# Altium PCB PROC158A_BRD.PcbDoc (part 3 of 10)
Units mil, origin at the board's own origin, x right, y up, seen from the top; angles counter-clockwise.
Board outline 3346.45 x 4921.26 mil, 8 copper layers (Top Layer, GND1, SIG1, PWR1, PWR2, SIG2, GND2, Bottom Layer), stack 54.534 mil thick; 718 components, 459 nets, 2307 pads, 1179 vias.
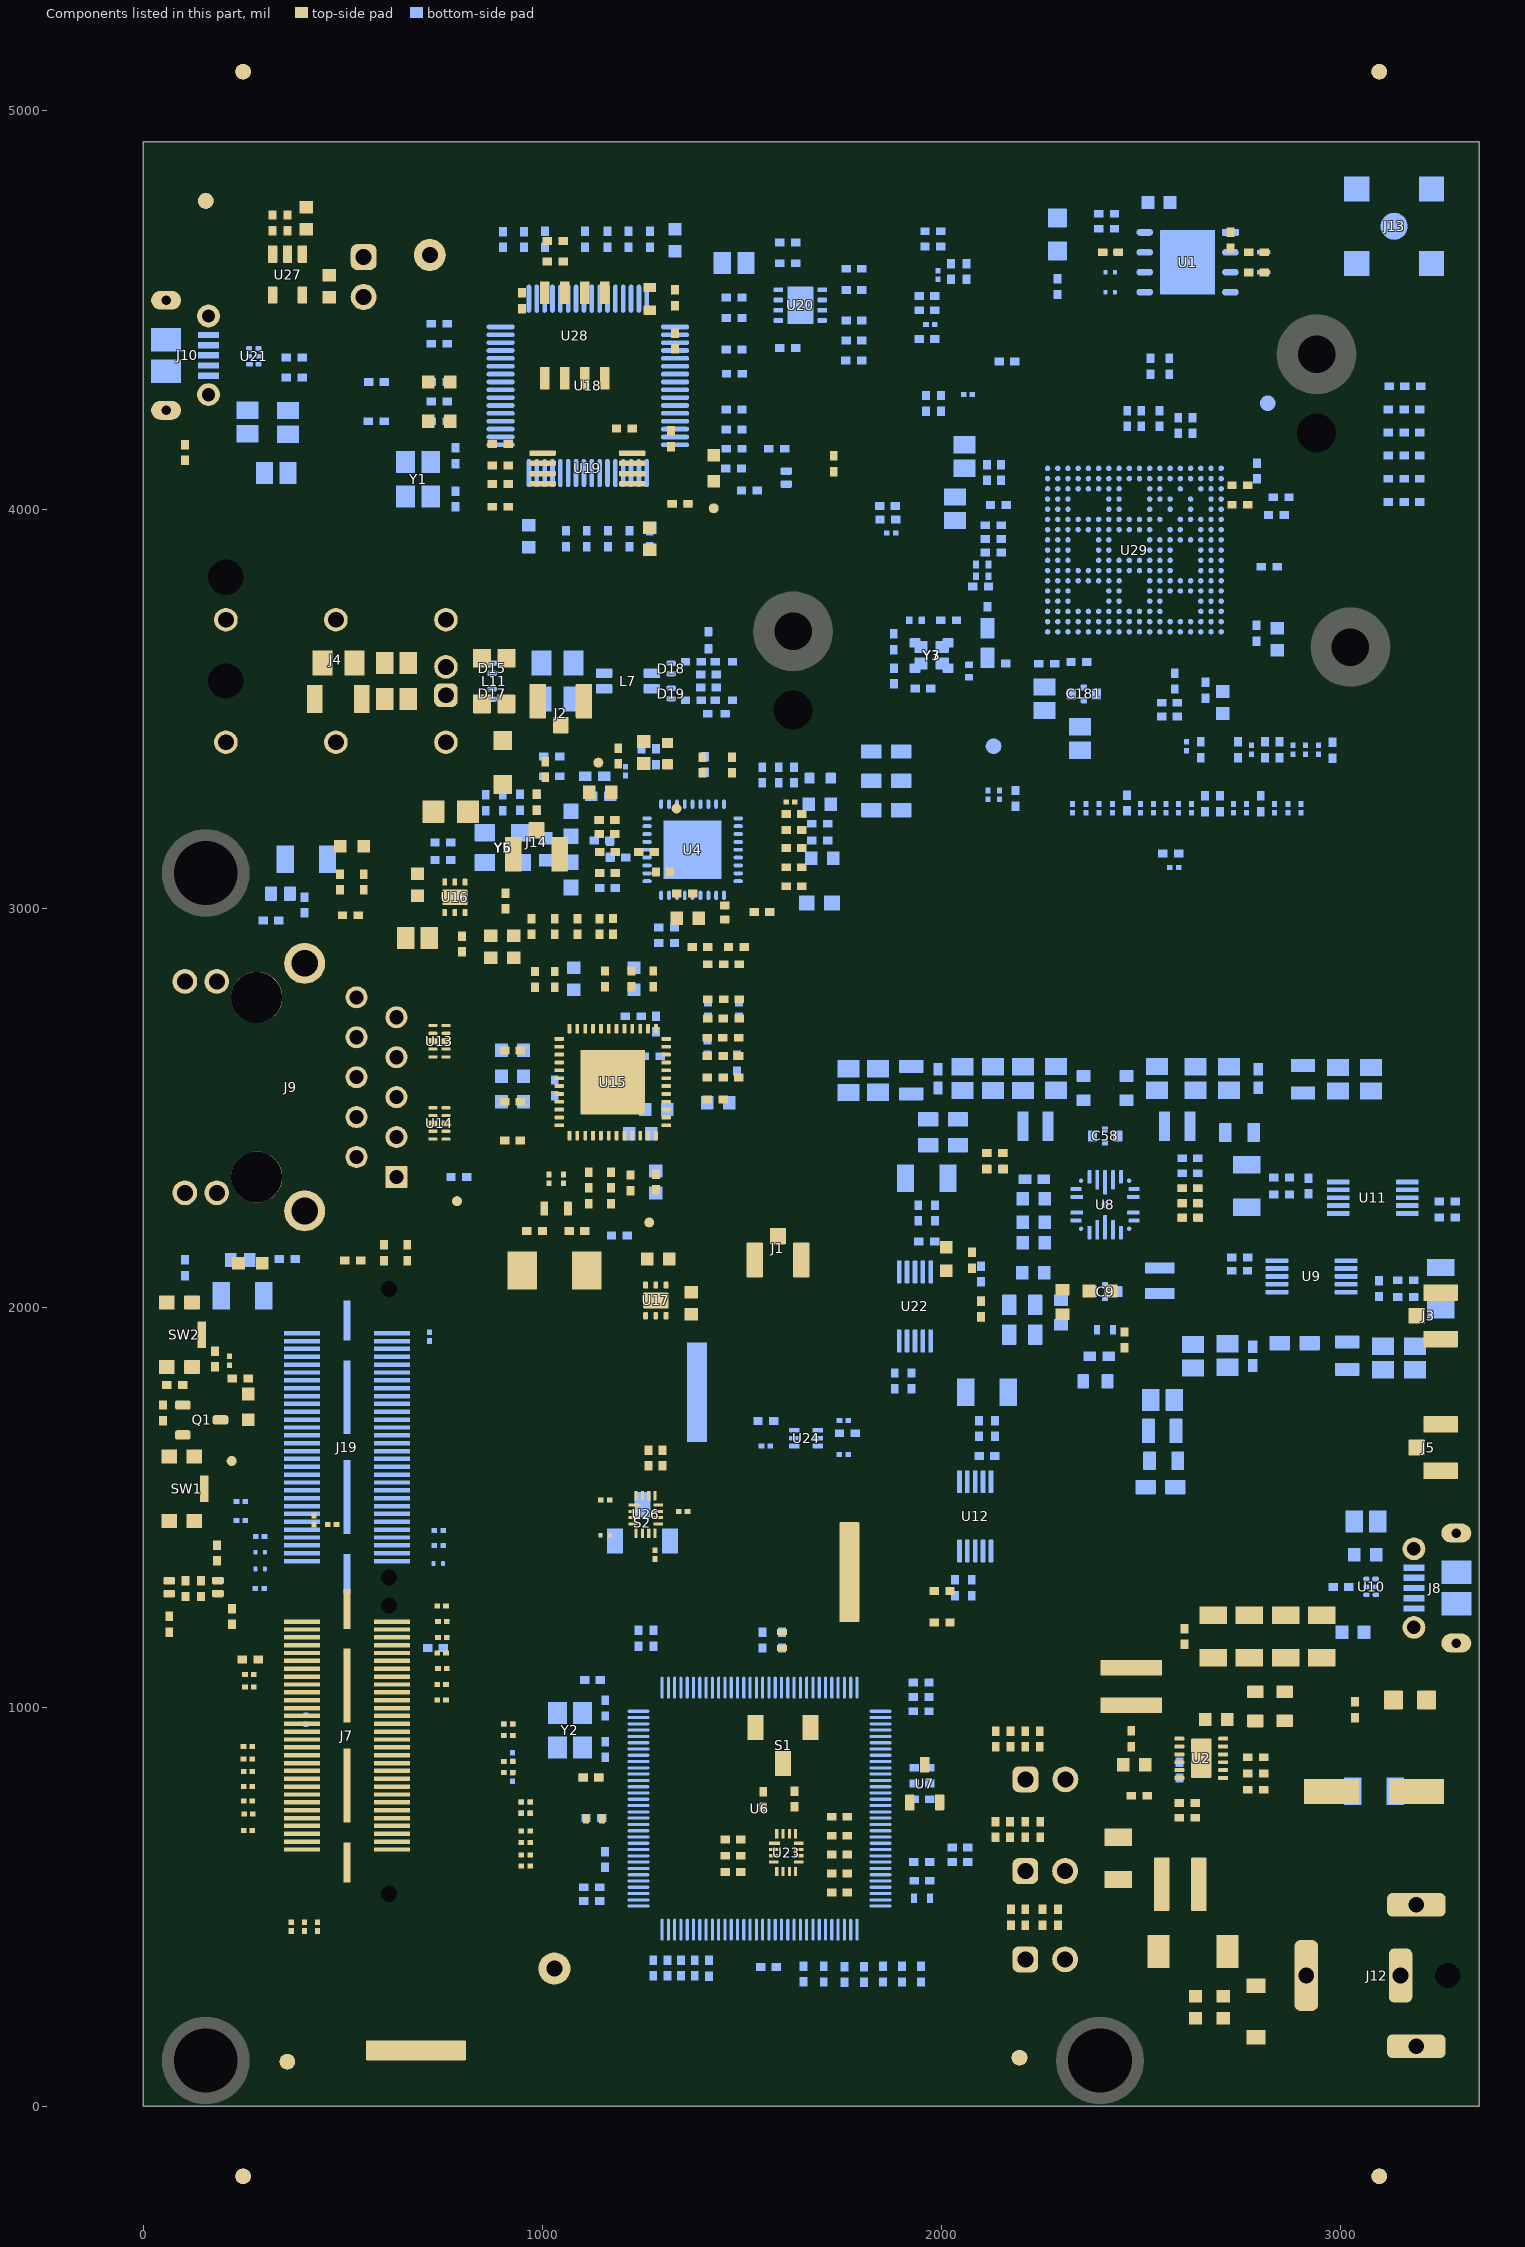
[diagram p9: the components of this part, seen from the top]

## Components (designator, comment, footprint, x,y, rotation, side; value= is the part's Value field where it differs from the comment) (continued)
R508 "CRCW02014K70FKED" 0201_033L 244.45,1467.61 r0 bottom value=4.70k
R512 "CRCW02014K70FKED" 0201_033L 740.29,1441.93 r0 bottom value=4.70k
S1 "CJS-1201TA" SW_CJS_1201A 1602.81,903.98 r180 top
S2 "CJS-1201TA" SW_CJS_1201A 1250.43,1461.4 r180 bottom
SW1 "KMR243GLFG" SW_KMR243GLFG 96.47,1547 r270 top
SW2 "KMR243GLFG" SW_KMR243GLFG 90.65,1932.78 r270 top
TP1 "TESTPOINT" TP_25MIL-SMT 1429,4003 r0 top
TP2 "TESTPOINT" TP_25MIL-SMT 1336,3251 r0 top
TP3 "TESTPOINT" TP_25MIL-SMT 1140,3365.81 r90 top
TP4 "TESTPOINT" TP_25MIL-SMT 221.49,1616.57 r180 top
TP5 "TESTPOINT" TP_25MIL-SMT 1267.43,2214.09 r90 top
TP6 "TESTPOINT" TP_25MIL-SMT 786.03,2267.32 r90 top
TP7 "5001" Keystone5001 717.82,4637.51 r90 bottom
TP9 "5001" Keystone5001 1030,345 r90 top
U1 "GD25B64CWAG" FP-GD25B64CWAG_WSON8-IPC_C 2616.14,4619.33 r180 bottom locked
U2 "LM63635DQDRRRQ1" DRR0012E-MFG 2650.36,871.52 r0 top
U4 "DP83TG720SWRNDRQ1" RND0036A 1376.2,3147.57 r0 bottom
U6 "TM4C1294NCPDTT3" PDT0128A 1543.78,745.39 r180 bottom
U7 "LM4040C25QDBZR" DBZ0003A_N 1957.44,808.38 r90 top
U8 "LP87725110RAGRQ1" RAG0024A-MFG 2409.48,2258.31 r180 bottom
U9 "INA228AIDGST" DGS0010A-MFG 2926.57,2078.86 r0 bottom
U10 "TPD4E004DRYR" DRY0006A 3075.82,1301 r180 bottom
U11 "INA228AIDGST" DGS0010A-MFG 3080,2275.91 r180 bottom
U12 "INA228AIDGST" DGS0010A-MFG 2084.09,1477.8 r90 bottom
U13 "TPD4E05U06DQAR" DQA0010A 742.07,2668.11 r0 top
U14 "TPD4E05U06DQAR" DQA0010A 742.07,2462.03 r0 top
U15 "DP83867ERGZR" RGZ0048B 1175.93,2565.54 r0 top
U16 "TPS73501DRVR" DRV0006A 780.58,3028.35 r90 top
U17 "TLV73310PQDRVRQ1" DRV0006A 1283.94,2018.66 r270 top
U18 "FT4232HL" LQFP64_N 1113.67,4309.69 r0 bottom
U19 "93LC46B-I/ST" TSSOP-8 1112.63,4102.86 r0 top
U20 "TPS79601DRBR" DRB0008B 1645.9,4511.81 r0 bottom
U21 "TPD4E004DRYR" DRY0006A 276.82,4383.75 r0 bottom
U22 "INA228AIDGST" DGS0010A-MFG 1933.06,2003.55 r90 bottom
U23 "TS3A5018RSVR" RSV0016A 1610.69,635.24 r0 top
U24 "TMP112AIDRLR" DRL0006A 1660.48,1673.65 r0 bottom
U26 "TS3A5018RSVR" RSV0016A 1258.31,1482.43 r0 top
U27 "TPS78417QDBVRQ1" DBV0005A-MFG 361.36,4588.41 r270 top
U28 "CAV24C02WE-GT3" SOIC-8 1080.83,4435.85 r90 top
U29 "xWR2544LOP" 0-IPC_C 2482.82,3898.25 r0 bottom locked
Y1 "NX3225SA-12.000M-STD-CRS-2" NDK_NX3225SA 688.79,4075.44 r0 bottom
Y2 "NX3225SA-16.000M-STD-CRS-2" NDK_NX3225SA 1068.77,941.56 r0 bottom
Y3 "NX2016SA-50M-STD-CZS-3" FP-NX2016SA-50M-STD-CZS-3_SMT4_2MM0_1MM6-MFG 1974.89,3634.94 r0 bottom
Y4 "ABM3-25.000MHZ-D2Y-T" XTAL_ABM3 1030.27,2093.9 r0 top
Y5 "ABM8AIG-25.000MHZ-12-2Z-T3" Abracon_ABM8AIG 901.05,3152.84 r270 bottom
Y6 "CDC6CE02500CDLE" DLE0004A-MFG 902,3152.81 r270 bottom
Y7 "CDC6CE05000CDLE" DLE0004A-MFG 1974.89,3634.2 r270 bottom
ZZ1 "This Assembly Note is for PCB labels only" AssemblyNoteLabel 187.12,5373.66 r0 top
ZZ2 "These assemblies are ESD sensitive, ESD precautions shall be observed." AssemblyNote 187.12,5264.77 r0 top
ZZ3 "These assemblies must be clean and free from flux and all contaminants. Use of no clean flux is not acceptable." AssemblyNote 187.12,5176.21 r0 top
ZZ4 "These assemblies must comply with workmanship standards IPC-A-610 Class 2, unless otherwise specified." AssemblyNote 187.12,5087.66 r0 top

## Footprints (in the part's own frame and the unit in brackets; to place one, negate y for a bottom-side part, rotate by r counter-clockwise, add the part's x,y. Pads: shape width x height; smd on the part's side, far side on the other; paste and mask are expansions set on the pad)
0-IPC_C [mm]
  round 0.349 smd paste+0 mask+0: A1(-5.525,5.2) A2(-4.875,5.2) A3(-4.225,5.2) A4(-3.575,5.2) A5(-2.925,5.2) A6(-2.275,5.2) A7(-1.625,5.2) A8(-0.975,5.2) A9(-0.325,5.2) A10(0.325,5.2) A11(0.975,5.2) A12(1.625,5.2) A13(2.275,5.2) A14(2.925,5.2) A15(3.575,5.2) A16(4.225,5.2) A17(4.875,5.2) A18(5.525,5.2) B1(-5.525,4.55) B2(-4.875,4.55) B3(-4.225,4.55) B4(-3.575,4.55) B5(-2.925,4.55) B6(-2.275,4.55) B7(-1.625,4.55) B8(-0.975,4.55) B9(-0.325,4.55) B10(0.325,4.55) B11(0.975,4.55) B12(1.625,4.55) B13(2.275,4.55) B14(2.925,4.55) B15(3.575,4.55) B16(4.225,4.55) B17(4.875,4.55) B18(5.525,4.55) C1(-5.525,3.9) C2(-4.875,3.9) C3(-4.225,3.9) C4(-3.575,3.9) C5(-2.925,3.9) C6(-2.275,3.9) C7(-1.625,3.9) C8(-0.975,3.9) C9(-0.325,3.9) C10(0.325,3.9) C11(0.975,3.9) C12(1.625,3.9) C16(4.225,3.9) C17(4.875,3.9) C18(5.525,3.9) D1(-5.525,3.25) D2(-4.875,3.25) D3(-4.225,3.25) D7(-1.625,3.25) D8(-0.975,3.25) D11(0.975,3.25) D12(1.625,3.25) D16(4.225,3.25) D17(4.875,3.25) D18(5.525,3.25) E1(-5.525,2.6) E2(-4.875,2.6) E3(-4.225,2.6) E7(-1.625,2.6) E8(-0.975,2.6) E11(0.975,2.6) E12(1.625,2.6) E13(2.275,2.6) E14(2.925,2.6) E15(3.575,2.6) E16(4.225,2.6) E17(4.875,2.6) E18(5.525,2.6) F1(-5.525,1.95) F2(-4.875,1.95) F3(-4.225,1.95) F4(-3.575,1.95) F5(-2.925,1.95) F6(-2.275,1.95) F7(-1.625,1.95) F8(-0.975,1.95) F11(0.975,1.95) F12(1.625,1.95) F13(2.275,1.95) F14(2.925,1.95) F15(3.575,1.95) F16(4.225,1.95) F17(4.875,1.95) F18(5.525,1.95) G1(-5.525,1.3) G2(-4.875,1.3) G3(-4.225,1.3) G4(-3.575,1.3) G5(-2.925,1.3) G6(-2.275,1.3) G7(-1.625,1.3) G8(-0.975,1.3) G9(-0.325,1.3) G10(0.325,1.3) G11(0.975,1.3) G12(1.625,1.3) G13(2.275,1.3) G16(4.225,1.3) G17(4.875,1.3) G18(5.525,1.3) H1(-5.525,0.65) H2(-4.875,0.65) H3(-4.225,0.65) H6(-2.275,0.65) H7(-1.625,0.65) H8(-0.975,0.65) H9(-0.325,0.65) H10(0.325,0.65) H11(0.975,0.65) H12(1.625,0.65) H13(2.275,0.65) H16(4.225,0.65) H17(4.875,0.65) H18(5.525,0.65) J1(-5.525,0) J2(-4.875,0) J3(-4.225,0) J6(-2.275,0) J7(-1.625,0) J11(0.975,0) J12(1.625,0) J13(2.275,0) J16(4.225,0) J17(4.875,0) J18(5.525,0) K2(-4.875,-0.65) K3(-4.225,-0.65) K6(-2.275,-0.65) K7(-1.625,-0.65) K11(0.975,-0.65) K12(1.625,-0.65) K13(2.275,-0.65) K14(2.925,-0.65) K15(3.575,-0.65) K16(4.225,-0.65) K17(4.875,-0.65) K18(5.525,-0.65) L1(-5.525,-1.3) L2(-4.875,-1.3) L3(-4.225,-1.3) L4(-3.575,-1.3) L5(-2.925,-1.3) L6(-2.275,-1.3) L7(-1.625,-1.3) L8(-0.975,-1.3) L9(-0.325,-1.3) L10(0.325,-1.3) L11(0.975,-1.3) L13(2.275,-1.3) L14(2.925,-1.3) L16(4.225,-1.3) L17(4.875,-1.3) L18(5.525,-1.3) M1(-5.525,-1.95) M2(-4.875,-1.95) M3(-4.225,-1.95) M4(-3.575,-1.95) M5(-2.925,-1.95) M6(-2.275,-1.95) M7(-1.625,-1.95) M8(-0.975,-1.95) M9(-0.325,-1.95) M10(0.325,-1.95) M11(0.975,-1.95) M12(1.625,-1.95) M14(2.925,-1.95) M15(3.575,-1.95) M16(4.225,-1.95) M17(4.875,-1.95) M18(5.525,-1.95) N1(-5.525,-2.6) N2(-4.875,-2.6) N3(-4.225,-2.6) N7(-1.625,-2.6) N8(-0.975,-2.6) N11(0.975,-2.6) N13(2.275,-2.6) N15(3.575,-2.6) N17(4.875,-2.6) N18(5.525,-2.6) P1(-5.525,-3.25) P2(-4.875,-3.25) P3(-4.225,-3.25) P7(-1.625,-3.25) P8(-0.975,-3.25) P11(0.975,-3.25) P12(1.625,-3.25) P13(2.275,-3.25) P15(3.575,-3.25) P17(4.875,-3.25) P18(5.525,-3.25) R1(-5.525,-3.9) R2(-4.875,-3.9) R3(-4.225,-3.9) R4(-3.575,-3.9) R5(-2.925,-3.9) R6(-2.275,-3.9) R7(-1.625,-3.9) R8(-0.975,-3.9) R11(0.975,-3.9) R12(1.625,-3.9) R14(2.925,-3.9) R16(4.225,-3.9) R17(4.875,-3.9) R18(5.525,-3.9) T1(-5.525,-4.55) T2(-4.875,-4.55) T3(-4.225,-4.55) T4(-3.575,-4.55) T5(-2.925,-4.55) T6(-2.275,-4.55) T7(-1.625,-4.55) T8(-0.975,-4.55) T9(-0.325,-4.55) T10(0.325,-4.55) T11(0.975,-4.55) T12(1.625,-4.55) T13(2.275,-4.55) T14(2.925,-4.55) T15(3.575,-4.55) T16(4.225,-4.55) T17(4.875,-4.55) T18(5.525,-4.55) U1(-5.525,-5.2) U2(-4.875,-5.2) U3(-4.225,-5.2) U4(-3.575,-5.2) U5(-2.925,-5.2) U6(-2.275,-5.2) U7(-1.625,-5.2) U8(-0.975,-5.2) U9(-0.325,-5.2) U10(0.325,-5.2) U11(0.975,-5.2) U12(1.625,-5.2) U13(2.275,-5.2) U14(2.925,-5.2) U15(3.575,-5.2) U16(4.225,-5.2) U17(4.875,-5.2) U18(5.525,-5.2)
  oval 0.349x0.349 smd paste+0 mask+0: K1(-5.525,-0.65)
  silkscreen extent -6.96,-6 6.2,6, body extent -6.2,-6 6.2,6, height 1.24
142-0711-201 [mil] "Emerson Connectivity recommended land pattern"
  round 68 smd: 1(0,0)
  rect 63x63 smd: 2(-93.5,-93.5) 2(-93.5,93.5) 2(93.5,-93.5) 2(93.5,93.5)
  Top Layer region: -47.5,64.83 -57.02,57.02 -67.05,44.8 -74.5,30.86 -79.09,15.73 -80.64,0 -79.09,-15.73 -74.5,-30.86 -67.05,-44.8 -57.02,-57.02 -47.5,-64.83 -47.5,-140 -140.5,-140 -140.5,140 -47.5,140
  Top Layer region: 140.5,-140 47.5,-140 47.5,-64.83 57.02,-57.02 67.05,-44.8 74.5,-30.86 79.09,-15.73 80.64,0 79.09,15.73 74.5,30.86 67.05,44.8 57.02,57.02 47.5,64.83 47.5,140 140.5,140
  body extent -125,-125 125,125, height 349
0201_033L [mm] "0201"
  rect 0.36x0.32 smd mask+0.048: 1(-0.28,0) 2(0.28,0)
  body extent -0.31,-0.16 0.31,0.16, height 0.33
0201L [mm] "Data from Kemet datasheet CC101_COM dated 7/28/11"
  rect 0.36x0.32 smd mask+0.048: 1(-0.28,0) 2(0.28,0)
  body extent -0.31,-0.16 0.31,0.16, height 0.26
0402 [mm] "0402 from SM-752 data"
  rect 0.8x0.6 smd: 1(-0.6,0) 2(0.6,0)
  silkscreen extent -1.22,-0.52 1.22,0.52, body extent -0.55,-0.3 0.55,0.3, height 0.6
0402_065L [mm] "0402"
  rect 0.6x0.5 smd: 1(-0.5,0) 2(0.5,0)
  body extent -0.55,-0.3 0.55,0.3, height 0.65
0402_070 [mil] "SMD, 2-Leads, Body 1.2x0.7mm, Height 0.7mm"
  rect 15x24 smd: 1(-20,0) 2(20,0)
  body extent -24,-14 24,14, height 28
0402L [mm] "0402 from SM-752 data"
  rect 0.6x0.5 smd: 1(-0.5,0) 2(0.5,0)
  body extent -0.55,-0.3 0.55,0.3, height 0.6
0402S [mil] "Based on C0402S footprint from PADS legacy"
  rect 15x24 smd: 1(-20,0) 2(20,0)
  body extent -22,-12 22,12, height 24
0603 [mm] "0603 from SM-752 data"
  rect 1x0.95 smd: 1(-0.8,0) 2(0.8,0)
  silkscreen extent -1.52,-0.69 1.52,0.69, body extent -0.87,-0.47 0.87,0.47, height 1
0603L [mm] "0603 from SM-752 data"
  rect 0.8x0.85 smd: 1(-0.7,0) 2(0.7,0)
  silkscreen extent -0.07,-0.33 0.07,0.33, body extent -0.87,-0.47 0.87,0.47, height 1
0805_155 [mm] "SMD, 2-Leads, Body 2x1.25mm"
  rrect12% 0.825x1.55 smd: 1(-0.875,0) 2(0.875,0)
  silkscreen extent -0.15,-0.77 0.15,0.77, body extent -1.15,-0.77 1.15,0.77, height 1.55
0805_HV [mil] "0805 with 30mil clearance between pads"
  rect 50x63 smd: 1(-40,0) 2(40,0)
  silkscreen extent -74,-40 74,40, body extent -43,-29 43,29, height 57
0805L [mm] "0805 from SM-752 data"
  rect 1.1x1.4 smd: 1(-0.75,0) 2(0.75,0)
  body extent -1.1,-0.72 1.1,0.72, height 1.45
1206_180L [mm] "1206_180"
  rect 1.1x1.75 smd: 1(-1.35,0) 2(1.35,0)
  silkscreen extent -0.4,-0.77 0.4,0.77, body extent -1.75,-0.95 1.75,0.95, height 1.8
1206L [mm] "1206 from SM-752 data"
  rect 1.1x1.75 smd: 1(-1.35,0) 2(1.35,0)
  silkscreen extent -0.4,-0.77 0.4,0.77, body extent -1.7,-0.9 1.7,0.9, height 1.35
-UKCA_Filled [mil]
  silkscreen extent -118,-118 118,118
Abracon_ABM8AIG [mm] "SMD, 4-Leads, Body 3.2x2.5mm"
  rrect9% 1.1x1.3 smd: 1(-0.95,1.15) 2(-0.95,-1.15) 3(0.95,-1.15) 4(0.95,1.15)
  silkscreen extent -1.8,1.3 -1.28,2.07, body extent -1.3,-1.65 1.3,1.65, height 0.8
AssemblyNote [mil] "Assembly Note"
AssemblyNoteLabel [mil] "Assembly Note for PCB Labels"
CE_Mark_5mm [mil] "Minimum text height for CE Mark"
  silkscreen extent -138,-98 138,98
CONN_105017-0001 [mm] "Molex Micro USB-B"
  rect 0.4x1.35 smd: 1(-1.3,1.35) 2(-0.65,1.35) 3(0,1.35) 4(0.65,1.35) 5(1.3,1.35)
  oval 1.2x1.9 hole 0.6 slot 1.3 at 90 deg: 6(-3.5,-1.35) 9(3.5,-1.35)
  rect 1.5x1.9 smd: 7(-1,-1.35) 8(1,-1.35)
  round 1.45 hole 0.85: 10(2.5,1.35) 11(-2.5,1.35)
  Top Layer region: 3.5,-2.3 2.3,-2.3 2.3,-0.4 3.5,-0.4
  Top Layer region: -3.5,-0.4 -2.3,-0.4 -2.3,-2.3 -3.5,-2.3
  silkscreen extent -4.1,-0.2 4.1,1.4, body extent -4.1,-3.93 4.1,1.5, height 2.72
CUI_PJ-063AH [mm] "DC POWER JACK, R/A, TH"
  rrect50% 1.5x4.5 hole 1 square: 1(-4.5,0)
  rrect50% 1.5x3.45 hole 1 square: 2(1.5,0)
  oval 1.35x1.3 hole 1.6 unplated mask+0.102: ALIGN(4.5,0)
  rrect50% 3.75x1.5 hole 1 square: S1(2.5,-4.5) S2(2.5,4.5)
  body extent -5.5,-5.15 7.5,5.15, height 9
DBV0005A-MFG [mm]
  rrect17% 1.1x0.6 smd paste+0 mask+0: 1(-1.3,0.95) 2(-1.3,0) 3(-1.3,-0.95) 4(1.3,-0.95) 5(1.3,0.95)
  silkscreen extent -1.5,-1.53 0.87,2.01, body extent -1.95,-1.78 1.95,1.78, height 0.25
DBZ0003A_N [mm] "SOT23, 3-Leads, Body 2.9x1.3mm, Pitch 0.95mm, Lead Span 2.4mm, IPC Medium Density"
  rrect17% 1x0.6 smd: 1(-1.2,0.95) 2(-1.2,-0.95) 3(1.2,0)
  silkscreen extent 0.2,-1.5 0.7,1.5, body extent -1.26,-1.46 1.26,1.46, height 0.98
DGS0010A-MFG [mm]
  rrect33% 1.45x0.3 smd paste+0 mask+0: 1(-2.2,1) 2(-2.2,0.5) 3(-2.2,0) 4(-2.2,-0.5) 5(-2.2,-1) 6(2.2,-1) 7(2.2,-0.5) 8(2.2,0) 9(2.2,0.5) 10(2.2,1)
  silkscreen extent -3.6,-1.55 1.05,1.55, body extent -2.45,-1.5 2.45,1.5, height 1.1
DLE0004A-MFG [mm]
  rrect17% 0.6x0.7 smd paste-1000 mask+0: 1(-0.8,1.05) 2(-0.8,-1.05) 3(0.8,-1.05) 4(0.8,1.05)
  silkscreen extent -1.99,-1.65 1.3,2.36, body extent -1.25,-1.6 1.25,1.6, height 1
DPY0002A [mm] "X1SON-2"
  rrect57% 0.35x0.6 smd paste-0.5 mask-0.05: 1(-0.325,0) 2(0.325,0)
  rrect33% 0.3x0.5 on Bottom Paste: 1S(-0.35,0) 2S(0.35,0)
  silkscreen extent -0.85,-0.02 -0.8,0.03, body extent -0.5,-0.3 0.5,0.3, height 0.45
DQA0010A [mm] "SON, 10-Leads, Body 1x2.5mm, Pitch 0.5mm, TI Recommended"
  rrect50% 0.565x0.2 smd: 1(-0.417,1) 2(-0.417,0.5) 4(-0.417,-0.5) 5(-0.417,-1) 6(0.417,-1) 7(0.417,-0.5) 9(0.417,0.5) 10(0.417,1)
  rrect28% 0.565x0.36 on Top Paste: 3(-0.417,0) 8(0.417,0)
  rrect25% 0.565x0.4 smd paste-0.2: 3(-0.417,0) 8(0.417,0)
  silkscreen extent -0.67,-1.45 0.55,1.45, body extent -0.55,-1.3 0.55,1.3, height 0.56
DRB0008B [mm] "SON, 8-Leads, Body 3x3mm, Pitch 0.65mm, Thermal Pad 2.4x1.65mm, TI Recommended"
  rrect33% 0.6x0.3 smd: 1(-1.4,0.975) 2(-1.4,0.325) 3(-1.4,-0.325) 4(-1.4,-0.975) 5(1.4,-0.975) 6(1.4,-0.325) 7(1.4,0.325) 8(1.4,0.975)
  rrect9% 1.47x1.06 on Bottom Paste: 9(0,-0.63) 9(0,0.63)
  rrect6% 1.65x2.4 smd paste-1.2: 9(0,0)
  silkscreen extent -1.73,-1.73 1.73,1.73, body extent -1.5,-1.5 1.5,1.5, height 0.96
DRL0006A [mm] "SOTFL, 6-Flat Leads, Body 1.2x1.6x0.6mm, Pitch 0.5mm, TI recommended"
  rrect33% 0.67x0.3 smd: 1(-0.74,0.5) 2(-0.74,0) 3(-0.74,-0.5) 4(0.74,-0.5) 5(0.74,0) 6(0.74,0.5)
  silkscreen extent -0.9,-0.95 0.5,0.95, body extent -0.8,-0.8 0.8,0.8, height 0.61
DRR0012E-MFG [mm]
  rrect40% 0.62x0.25 smd paste+0 mask+0: 1(-1.39,1.25) 2(-1.39,0.75) 3(-1.39,0.25) 4(-1.39,-0.25) 5(-1.39,-0.75) 6(-1.39,-1.25) 7(1.39,-1.25) 8(1.39,-0.75) 9(1.39,-0.25) 10(1.39,0.25) 11(1.39,0.75) 12(1.39,1.25)
  rrect8% 1.3x2.5 smd paste-1000 mask+0: 13(0,0)
  silkscreen extent -2.37,-1.75 1.55,1.75, body extent -1.8,-1.65 1.8,1.65, height 0.25
DRV0006A [mm] "SON, 6-Leads, Body 2x2mm, Pitch 0.65mm, Thermal Pad 1.6x1mm, TI Recommended"
  rrect33% 0.45x0.3 smd: 1(-0.975,0.65) 2(-0.975,0) 3(-0.975,-0.65) 4(0.975,-0.65) 5(0.975,0) 6(0.975,0.65)
  rrect14% 1x0.7 on Top Paste: 7(0,0.45) 7(0,-0.45)
  rrect10% 1x1.6 smd paste-0.5: 7(0,0)
  silkscreen extent -1.05,-1.2 1.05,1.2, body extent -1.05,-1.05 1.05,1.05, height 0.81
DRY0006A [mm] "USON-6"
  rrect67% 0.45x0.3 smd paste-0.05 mask-0.05: 1(-0.275,0.5)
  rrect67% 0.4x0.3 smd paste-0.05 mask-0.05: 2(-0.3,0) 3(-0.3,-0.5) 4(0.3,-0.5) 5(0.3,0) 6(0.3,0.5)
  body extent -0.5,-0.72 0.5,0.72, height 0.58
ESD_Overlay_Small [mil]
  silkscreen extent -62,-48 64,61
FCC_disclaimer [mil]
Fiducial10-20 [mm]
  round 1 smd paste-1 mask+0.5: 1(0,0)
  Top Layer keep-out circle w1.178: c0,0 r0.5
"FP-1909763-1_SMT_JACK _CONN-MFG" [mm]
  rrect10% 1x1.05 smd paste+0 mask+0: 1(0,-1.6)
  rrect10% 1.05x2.2 smd paste+0 mask+0: 2(-1.475,-0.075) 3(1.475,-0.075)
  silkscreen extent -1.43,-2.8 1.43,1.5, body extent -2.1,-2.22 2.1,1.6, height 0.25
FP-ADL32VHR-3R9M_SMT_3MM2_2MM5-MFG [mm]
  rrect9% 1.2x1.15 smd paste+0 mask+0: 1(-1.45,0.775) 2(-1.45,-0.775) 3(1.45,-0.775) 4(1.45,0.775)
  silkscreen extent -2.75,-1.45 0.48,1.45, body extent -1.95,-1.25 1.95,1.25, height 2.5
"FP-BLM18KG601SH1_0603 (1608 Metric)-MFG" [mm]
  rrect15% 0.65x0.7 smd paste+0 mask+0: 1(-0.675,0) 2(0.675,0)
  silkscreen extent -0.87,-0.75 0.87,0.75, body extent -0.8,-0.4 0.8,0.4, height 0.95
FP-C0603C104K4RACAUTO_0603-MFG [mm]
  rrect13% 0.75x0.9 smd paste+0 mask+0: 1(-0.6,0) 2(0.6,0)
  silkscreen extent -0.87,-0.85 0.88,0.85, body extent -0.8,-0.4 0.8,0.4, height 0.87
FP-CC1206KKX7RCBB472_1206-MFG [mm]
  rrect10% 1x1.8 smd paste+0 mask+0: 1(-1.5,0) 2(1.5,0)
  silkscreen extent -0.63,-0.9 0.63,0.9, body extent -2.2,-1.25 2.2,1.25, height 0.25
FP-CGA4J1X7R1H475K125AC_0805-MFG [mm]
  rrect13% 0.8x1.05 smd paste+0 mask+0: 1(-0.925,0) 2(0.925,0)
  silkscreen extent -0.15,-0.72 0.15,0.72, body extent -1.43,-0.82 1.43,0.82, height 0.25
FP-CRCW04024K22FKED_0402-MFG [mm]
  rrect17% 0.6x0.6 smd paste+0 mask+0: 1(-0.525,0) 2(0.525,0)
  silkscreen extent -0.53,-0.7 0.53,0.57, body extent -0.92,-0.4 0.92,0.4, height 0.25
FP-CRCW06031M00FKEAC_0603-MFG [mm]
  rrect20% 0.5x0.9 smd paste+0 mask+0: 1(-0.75,0) 2(0.75,0)
  silkscreen extent -0.82,-0.85 0.82,0.85, body extent -1.1,-0.55 1.1,0.55, height 0.25
FP-DLW32MH101XT2_1210-MFG [mm]
  rrect17% 1.05x0.6 smd paste+0 mask+0: 1(-1.525,-0.5) 2(1.525,-0.5) 3(1.525,0.5) 4(-1.525,0.5)
  silkscreen extent -2.23,-1.66 1.7,1.35, body extent -1.6,-1.25 1.6,1.25, height 2.5
FP-ERJ-1GNF33R2C_0201-MFG [mm]
  rrect40% 0.25x0.3 smd paste+0 mask+0: 1(-0.3,0) 2(0.3,0)
  silkscreen extent -0.32,-0.54 0.32,0.54, body extent -0.3,-0.15 0.3,0.15, height 0.26
FP-GCJ188C70J475KE02J_0603-MFG [mm]
  rrect13% 0.75x0.9 smd paste+0 mask+0: 1(-0.775,0) 2(0.775,0)
  silkscreen extent -0.9,-0.87 0.9,0.87, body extent -0.8,-0.4 0.8,0.4, height 1
FP-GCM1555C1H3R9BA16D_0402-MFG [mm]
  rrect25% 0.4x0.5 smd paste+0 mask+0: 1(-0.4,0) 2(0.4,0)
  silkscreen extent -0.53,-0.65 0.53,0.65, body extent -0.5,-0.25 0.5,0.25, height 0.55
FP-GD25B64CWAG_WSON8-IPC_C [mm]
  rrect23% 1.059x0.436 smd paste+0 mask+0: 1(-2.727,1.905)
  rrect100% 1.059x0.436 smd paste+0 mask+0: 2(-2.727,0.635) 3(-2.727,-0.635) 4(-2.727,-1.905) 5(2.727,-1.905) 6(2.727,-0.635) 7(2.727,0.635) 8(2.727,1.905)
  rrect3% 3.5x4.1 smd paste-1000 mask+0: 9(0,0)
  silkscreen extent -3.93,-2.5 3,2.5, body extent -3,-2.5 3,2.5, height 0.8
FP-GRT155R70J105KE01D_0402-MFG [mm]
  rrect25% 0.4x0.5 smd paste+0 mask+0: 1(-0.4,0) 2(0.4,0)
  silkscreen extent -0.02,-0.55 0.53,0.63, body extent -0.5,-0.25 0.5,0.25, height 0.55
FP-HCJ0603ZT0R00_0603-MFG [mm]
  rrect11% 1.3x0.92 smd paste+0 mask+0: 1(-0.95,0) 2(0.95,0)
  silkscreen extent -0.9,-0.83 0.9,0.83, body extent -0.8,-0.4 0.8,0.4, height 0.7
FP-HCJ0805ZT0R00_0805-MFG [mm]
  rrect7% 1.4x1.44 smd paste+0 mask+0: 1(-1.1,0) 2(1.1,0)
  silkscreen extent 0,-0.72 0,0.72, body extent -1.9,-0.82 1.9,0.82, height 0.25
FP-KGM05ACG1H220FH_0402-MFG [mm]
  rrect20% 0.6x0.5 smd paste+0 mask+0: 1(-0.55,0) 2(0.55,0)
  silkscreen extent -0.55,-0.63 0.55,0.63, body extent -0.5,-0.25 0.5,0.25, height 0.56
FP-KGM05ACG1H470FH_0402-MFG [mm]
  rrect20% 0.6x0.5 smd paste+0 mask+0: 1(-0.55,0) 2(0.55,0)
  silkscreen extent -0.55,-0.63 0.55,0.63, body extent -0.5,-0.25 0.5,0.25, height 0.56
FP-LPJG16414A4NL_CONN_RJ45-MFG [mm]
  rrect7% 1.4x1.4 hole 0.9 paste-1000 mask+0: 1(-5.715,9.015)
  round 1.4 hole 0.9 paste-1000 mask+0: 2(-4.445,6.475) 3(-3.175,9.015) 4(-1.905,6.475) 5(-0.635,9.015) 6(0.635,6.475) 7(1.905,9.015) 8(3.175,6.475) 9(4.445,9.015) 10(5.715,6.475)
  round 1.57 hole 1.02 paste-1000 mask+0: 11(6.725,-2.415) 12(6.725,-4.445) 13(-6.725,-2.415) 14(-6.725,-4.445)
  round 2.6 hole 1.7 paste-1000 mask+0: 15(-7.875,3.175) 16(7.875,3.175)
  round 3.25 hole 3.25 unplated paste-1000 mask+0: ""(-5.715,0.125) ""(5.715,0.125)
  silkscreen extent -9.72,-10.75 8.1,10.75, body extent -9.94,-10.88 9.87,10.63, height 15.47
FP-MPZ2012S101ATD25_0805-MFG [mm]
  rrect13% 0.8x1.2 smd paste+0 mask+0: 1(-0.9,0) 2(0.9,0)
  silkscreen extent -0.13,-0.72 0.13,0.72, body extent -1,-0.63 1,0.63, height 1.05
FP-NFM18HC105C1C3D_0603-MFG [mm]
  rrect17% 0.6x0.7 smd paste+0 mask+0: 1(-0.8,0) 3(0.8,0)
  rrect25% 0.4x0.4 smd paste+0 mask+0: 2(0,-0.4) 2(0,0.4)
  silkscreen extent -1.66,-0.97 0.85,0.97, body extent -0.8,-0.4 0.8,0.4, height 0.7
FP-NX2016SA-50M-STD-CZS-3_SMT4_2MM0_1MM6-MFG [mm]
  rrect13% 0.85x0.75 smd paste+0 mask+0: 1(-0.675,-0.525) 2(0.675,-0.525) 3(0.675,0.525) 4(-0.675,0.525)
  silkscreen extent -1.48,-1.57 1.48,0.85, body extent -1,-0.8 1,0.8, height 0.5
FP-SML-P12DTT86R_0402-MFG [mm]
  rrect20% 0.5x0.6 smd paste+0 mask+0: 1(-0.45,0) 2(0.45,0)
  silkscreen extent -1.38,-0.67 0.53,0.67, body extent -0.8,-0.43 0.8,0.43, height 0.25
FP-SML-P12YTT86R_0402-MFG [mm]
  rrect20% 0.5x0.6 smd paste+0 mask+0: 1(-0.45,0) 2(0.45,0)
  silkscreen extent -1.37,-0.67 0.53,0.67, body extent -0.8,-0.43 0.8,0.43, height 0.25
FP-XAL4030-472MEC_SMD2-MFG [mm]
  rrect10% 0.98x3.4 smd paste+0 mask+0: 1(-1.185,0) 2(1.185,0)
  silkscreen extent -2.15,-2.15 2.15,2.15, body extent -2,-2 2,2, height 3.1
IEC_HotSurface_Small [mil]
  silkscreen extent -107,-93 107,92
Johnson_128-0711-201 [mm] "UMC Straight Jack Receptacle, 50 Ohm, SMT"
  rrect10% 1x1.05 smd: 1(0,1.525)
  rrect10% 1.05x2.2 smd: 2(-1.475,0) 3(1.475,0)
  silkscreen extent -0.6,-1.3 0.6,-1.3, body extent -1.5,-1.55 1.5,1.55, height 1.25
Keystone5001 [mil] "For Keystone 500x miniature loop terminals"
  round 80 hole 40: 1(0,0)
  silkscreen extent -52,-52 52,52, body extent -49,-49 49,49, height 182
Label_650x200 [mil] "Thermal Transfer Label"
  round 1 on Mech14: 0(0,0)
  silkscreen extent -325,-100 325,100, body extent -325,-100 325,100, height 1
LQFP64_N [mm] "Thin QFP, 64-Leads, Body 10x10mm, Pitch 0.5mm, IPC Medium Density"
  oval 1.8x0.3 smd: 1(-5.55,3.75) 2(-5.55,3.25) 3(-5.55,2.75) 4(-5.55,2.25) 5(-5.55,1.75) 6(-5.55,1.25) 7(-5.55,0.75) 8(-5.55,0.25) 9(-5.55,-0.25) 10(-5.55,-0.75) 11(-5.55,-1.25) 12(-5.55,-1.75) 13(-5.55,-2.25) 14(-5.55,-2.75) 15(-5.55,-3.25) 16(-5.55,-3.75) 33(5.55,-3.75) 34(5.55,-3.25) 35(5.55,-2.75) 36(5.55,-2.25) 37(5.55,-1.75) 38(5.55,-1.25) 39(5.55,-0.75) 40(5.55,-0.25) 41(5.55,0.25) 42(5.55,0.75) 43(5.55,1.25) 44(5.55,1.75) 45(5.55,2.25) 46(5.55,2.75) 47(5.55,3.25) 48(5.55,3.75)
  oval 0.3x1.8 smd: 17(-3.75,-5.55) 18(-3.25,-5.55) 19(-2.75,-5.55) 20(-2.25,-5.55) 21(-1.75,-5.55) 22(-1.25,-5.55) 23(-0.75,-5.55) 24(-0.25,-5.55) 25(0.25,-5.55) 26(0.75,-5.55) 27(1.25,-5.55) 28(1.75,-5.55) 29(2.25,-5.55) 30(2.75,-5.55) 31(3.25,-5.55) 32(3.75,-5.55) 49(3.75,5.55) 50(3.25,5.55) 51(2.75,5.55) 52(2.25,5.55) 53(1.75,5.55) 54(1.25,5.55) 55(0.75,5.55) 56(0.25,5.55) 57(-0.25,5.55) 58(-0.75,5.55) 59(-1.25,5.55) 60(-1.75,5.55) 61(-2.25,5.55) 62(-2.75,5.55) 63(-3.25,5.55) 64(-3.75,5.55)
  silkscreen extent -5.67,-4.25 4.25,4.57, body extent -5,-5 5,5, height 1.6
"LS L29K_Red" [mm] "SMD, 2-Leads, Body 1.3x0.8mm"
  rect 0.8x0.8 smd paste-0.4: 1(-0.75,0) 2(0.75,0)
  silkscreen extent -0.1,-0.5 1.45,0.5, body extent -0.9,-0.45 0.9,0.45, height 0.67
NDK_NX3225SA [mm] "NDK"
  rect 1.2x1.4 smd: 1(-0.8,1.1) 2(-0.8,-1.1) 3(0.8,-1.1) 4(0.8,1.1)
  body extent -1.3,-1.65 1.3,1.65, height 0.7
Net-Tie_50milWide_30milLong [mil] "50mil net tie, no solder mask opening, no solder paste"
  rect 30x50 on Mid5 paste-20 mask-20: 1(-15,0) 2(15,0)
PDT0128A [mm] "Thin QFP, 128-Leads, Body 14x14mm, Pitch 0.4mm"
  oval 1.4x0.2 smd: 1(-7.7,6.2) 2(-7.7,5.8) 3(-7.7,5.4) 4(-7.7,5) 5(-7.7,4.6) 6(-7.7,4.2) 7(-7.7,3.8) 8(-7.7,3.4) 9(-7.7,3) 10(-7.7,2.6) 11(-7.7,2.2) 12(-7.7,1.8) 13(-7.7,1.4) 14(-7.7,1) 15(-7.7,0.6) 16(-7.7,0.2) 17(-7.7,-0.2) 18(-7.7,-0.6) 19(-7.7,-1) 20(-7.7,-1.4) 21(-7.7,-1.8) 22(-7.7,-2.2) 23(-7.7,-2.6) 24(-7.7,-3) 25(-7.7,-3.4) 26(-7.7,-3.8) 27(-7.7,-4.2) 28(-7.7,-4.6) 29(-7.7,-5) 30(-7.7,-5.4) 31(-7.7,-5.8) 32(-7.7,-6.2) 65(7.7,-6.2) 66(7.7,-5.8) 67(7.7,-5.4) 68(7.7,-5) 69(7.7,-4.6) 70(7.7,-4.2) 71(7.7,-3.8) 72(7.7,-3.4) 73(7.7,-3) 74(7.7,-2.6) 75(7.7,-2.2) 76(7.7,-1.8) 77(7.7,-1.4) 78(7.7,-1) 79(7.7,-0.6) 80(7.7,-0.2) 81(7.7,0.2) 82(7.7,0.6) 83(7.7,1) 84(7.7,1.4) 85(7.7,1.8) 86(7.7,2.2) 87(7.7,2.6) 88(7.7,3) 89(7.7,3.4) 90(7.7,3.8) 91(7.7,4.2) 92(7.7,4.6) 93(7.7,5) 94(7.7,5.4) 95(7.7,5.8) 96(7.7,6.2)
  oval 0.2x1.4 smd: 33(-6.2,-7.7) 34(-5.8,-7.7) 35(-5.4,-7.7) 36(-5,-7.7) 37(-4.6,-7.7) 38(-4.2,-7.7) 39(-3.8,-7.7) 40(-3.4,-7.7) 41(-3,-7.7) 42(-2.6,-7.7) 43(-2.2,-7.7) 44(-1.8,-7.7) 45(-1.4,-7.7) 46(-1,-7.7) 47(-0.6,-7.7) 48(-0.2,-7.7) 49(0.2,-7.7) 50(0.6,-7.7) 51(1,-7.7) 52(1.4,-7.7) 53(1.8,-7.7) 54(2.2,-7.7) 55(2.6,-7.7) 56(3,-7.7) 57(3.4,-7.7) 58(3.8,-7.7) 59(4.2,-7.7) 60(4.6,-7.7) 61(5,-7.7) 62(5.4,-7.7) 63(5.8,-7.7) 64(6.2,-7.7) 97(6.2,7.7) 98(5.8,7.7) 99(5.4,7.7) 100(5,7.7) 101(4.6,7.7) 102(4.2,7.7) 103(3.8,7.7) 104(3.4,7.7) 105(3,7.7) 106(2.6,7.7) 107(2.2,7.7) 108(1.8,7.7) 109(1.4,7.7) 110(1,7.7) 111(0.6,7.7) 112(0.2,7.7) 113(-0.2,7.7) 114(-0.6,7.7) 115(-1,7.7) 116(-1.4,7.7) 117(-1.8,7.7) 118(-2.2,7.7) 119(-2.6,7.7) 120(-3,7.7) 121(-3.4,7.7) 122(-3.8,7.7) 123(-4.2,7.7) 124(-4.6,7.7) 125(-5,7.7) 126(-5.4,7.7) 127(-5.8,7.7) 128(-6.2,7.7)
  silkscreen extent -7.7,-6.3 6.3,6.99, body extent -8,-8 8,8, height 1.07
RAG0024A-MFG [mm]
  round 0.278 smd paste+0 mask+0: 1(-1.53,1.53) 7(-1.53,-1.53) 13(1.53,-1.53) 19(1.53,1.53)
  rrect40% 0.7x0.25 smd paste+0 mask+0: 2(-1.85,1) 6(-1.85,-1) 14(1.85,-1) 18(1.85,1)
  rrect40% 0.8x0.25 smd paste+0 mask+0: 3(-1.8,0.5) 5(-1.8,-0.5) 15(1.8,-0.5) 17(1.8,0.5)
  round 0.45 smd paste-1000 mask+0: 4-16(0,0)
  rrect40% 0.25x0.86 smd paste+0 mask+0: 8(-1,-1.77) 12(1,-1.77) 20(1,1.77) 24(-1,1.77)
  rrect40% 0.25x1.225 smd paste+0 mask+0: 9(-0.5,-1.587) 11(0.5,-1.587) 21(0.5,1.587) 23(-0.5,1.587)
  rrect40% 0.25x1.55 smd paste+0 mask+0: 10(0,-1.425) 22(0,1.425)
  Top Layer region: 2.15,1.375 2.169,1.379 2.185,1.39 2.196,1.406 2.2,1.425 2.2,1.425 2.2,1.575 2.196,1.594 2.185,1.61 2.169,1.621 2.15,1.625 2.15,1.625 1.725,1.625 1.687,1.633 1.654,1.654 1.633,1.687 1.625,1.725 1.625,1.725 1.625,2.15 1.621,2.169 1.61,2.185 1.594,2.196 1.575,2.2 1.575,2.2 1.425,2.2 1.4,2.193 1.382,2.175 1.375,2.15 1.375,2.15 1.375,1.425 1.379,1.406 1.39,1.39 1.406,1.379 1.425,1.375 1.425,1.375
  Top Layer region: -2.15,-1.375 -2.169,-1.379 -2.185,-1.39 -2.196,-1.406 -2.2,-1.425 -2.2,-1.425 -2.2,-1.575 -2.196,-1.594 -2.185,-1.61 -2.169,-1.621 -2.15,-1.625 -2.15,-1.625 -1.725,-1.625 -1.687,-1.633 -1.654,-1.654 -1.633,-1.687 -1.625,-1.725 -1.625,-1.725 -1.625,-2.15 -1.621,-2.169 -1.61,-2.185 -1.594,-2.196 -1.575,-2.2 -1.575,-2.2 -1.425,-2.2 -1.406,-2.196 -1.39,-2.185 -1.379,-2.169 -1.375,-2.15 -1.375,-2.15 -1.375,-1.425 -1.379,-1.406 -1.39,-1.39 -1.406,-1.379 -1.425,-1.375 -1.425,-1.375
  Top Layer region: -2.15,-0.125 -2.175,-0.118 -2.193,-0.1 -2.2,-0.075 -2.2,-0.075 -2.2,0.075 -2.193,0.1 -2.175,0.118 -2.15,0.125 -2.15,0.125 -0.645,0.125 -0.626,0.129 -0.61,0.14 -0.599,0.156 -0.595,0.175 -0.595,0.175 -0.595,0.2 -0.588,0.225 -0.57,0.243 -0.545,0.25 -0.545,0.25 0.545,0.25 0.57,0.243 0.588,0.225 0.595,0.2 0.595,0.2 0.595,0.175 0.599,0.156 0.61,0.14 0.626,0.129 0.645,0.125 0.645,0.125 2.15,0.125 2.175,0.118 2.193,0.1 2.2,0.075 2.2,0.075 2.2,-0.075 2.193,-0.1 2.175,-0.118 2.15,-0.125 2.15,-0.125 0.645,-0.125 0.626,-0.129 0.61,-0.14 0.599,-0.156 0.595,-0.175 0.595,-0.175 0.595,-0.2 0.588,-0.225 0.57,-0.243 0.545,-0.25 0.545,-0.25 -0.545,-0.25 -0.57,-0.243 -0.588,-0.225 -0.595,-0.2 -0.595,-0.2 -0.595,-0.175 -0.599,-0.156 -0.61,-0.14 -0.626,-0.129 -0.645,-0.125 -0.645,-0.125
  Top Layer region: -2.15,1.375 -2.169,1.379 -2.185,1.39 -2.196,1.406 -2.2,1.425 -2.2,1.425 -2.2,1.575 -2.193,1.6 -2.175,1.618 -2.15,1.625 -2.15,1.625 -1.725,1.625 -1.687,1.633 -1.654,1.654 -1.633,1.687 -1.625,1.725 -1.625,1.725 -1.625,2.15 -1.618,2.175 -1.6,2.193 -1.575,2.2 -1.575,2.2 -1.425,2.2 -1.406,2.196 -1.39,2.185 -1.379,2.169 -1.375,2.15 -1.375,2.15 -1.375,1.425 -1.379,1.406 -1.39,1.39 -1.406,1.379 -1.425,1.375 -1.425,1.375
  Top Layer region: 2.15,-1.375 2.169,-1.379 2.185,-1.39 2.196,-1.406 2.2,-1.425 2.2,-1.425 2.2,-1.575 2.196,-1.594 2.185,-1.61 2.169,-1.621 2.15,-1.625 2.15,-1.625 1.725,-1.625 1.687,-1.633 1.654,-1.654 1.633,-1.687 1.625,-1.725 1.625,-1.725 1.625,-2.15 1.621,-2.169 1.61,-2.185 1.594,-2.196 1.575,-2.2 1.575,-2.2 1.425,-2.2 1.4,-2.193 1.382,-2.175 1.375,-2.15 1.375,-2.15 1.375,-1.425 1.379,-1.406 1.39,-1.39 1.406,-1.379 1.425,-1.375 1.425,-1.375
  silkscreen extent -2.88,-2.25 2.25,2.25, body extent -2,-2 2,2, height 1
RGZ0048B [mm] "QFN, 48-Leads, Body 7x7mm, Pitch 0.5mm, Thermal Pad 5.15x5.15mm, TI Recommended"
  rrect42% 0.6x0.24 smd: 1(-3.4,2.75) 2(-3.4,2.25) 3(-3.4,1.75) 4(-3.4,1.25) 5(-3.4,0.75) 6(-3.4,0.25) 7(-3.4,-0.25) 8(-3.4,-0.75) 9(-3.4,-1.25) 10(-3.4,-1.75) 11(-3.4,-2.25) 12(-3.4,-2.75) 25(3.4,-2.75) 26(3.4,-2.25) 27(3.4,-1.75) 28(3.4,-1.25) 29(3.4,-0.75) 30(3.4,-0.25) 31(3.4,0.25) 32(3.4,0.75) 33(3.4,1.25) 34(3.4,1.75) 35(3.4,2.25) 36(3.4,2.75)
  rrect42% 0.24x0.6 smd: 13(-2.75,-3.4) 14(-2.25,-3.4) 15(-1.75,-3.4) 16(-1.25,-3.4) 17(-0.75,-3.4) 18(-0.25,-3.4) 19(0.25,-3.4) 20(0.75,-3.4) 21(1.25,-3.4) 22(1.75,-3.4) 23(2.25,-3.4) 24(2.75,-3.4) 37(2.75,3.4) 38(2.25,3.4) 39(1.75,3.4) 40(1.25,3.4) 41(0.75,3.4) 42(0.25,3.4) 43(-0.25,3.4) 44(-0.75,3.4) 45(-1.25,3.4) 46(-1.75,3.4) 47(-2.25,3.4) 48(-2.75,3.4)
  rrect9% 1.17x1.17 on Top Paste: 49(-1.37,-1.37) 49(-1.37,0) 49(-1.37,1.37) 49(0,-1.37) 49(0,0) 49(0,1.37) 49(1.37,-1.37) 49(1.37,0) 49(1.37,1.37)
  rrect2% 4.1x4.1 smd paste-2.575: 49(0,0)
  silkscreen extent -3.72,-3.72 3.72,3.72, body extent -3.5,-3.5 3.5,3.5, height 1.01
RND0036A [mm] "TI"
  oval 0.6x0.25 smd: 1(-2.9,2) 2(-2.9,1.5) 3(-2.9,1) 4(-2.9,0.5) 5(-2.9,0) 6(-2.9,-0.5) 7(-2.9,-1) 8(-2.9,-1.5) 9(-2.9,-2) 19(2.9,-2) 20(2.9,-1.5) 21(2.9,-1) 22(2.9,-0.5) 23(2.9,0) 24(2.9,0.5) 25(2.9,1) 26(2.9,1.5) 27(2.9,2)
  oval 0.25x0.6 smd: 10(-2,-2.9) 11(-1.5,-2.9) 12(-1,-2.9) 13(-0.5,-2.9) 14(0,-2.9) 15(0.5,-2.9) 16(1,-2.9) 17(1.5,-2.9) 18(2,-2.9) 28(2,2.9) 29(1.5,2.9) 30(1,2.9) 31(0.5,2.9) 32(0,2.9) 33(-0.5,2.9) 34(-1,2.9) 35(-1.5,2.9) 36(-2,2.9)
  rect 3.7x3.7 smd paste-1.85: 37(0,0)
  silkscreen extent -3.17,-3.17 3.17,3.2, body extent -3,-3 3,3, height 0.81
RSV0016A [mm] "QFN, 16-Leads, Body 1.8x2.6mm, Pitch 0.4mm, TI Recommended"
  rect 0.7x0.2 smd: 1(-0.75,0.6)
  rect 0.6x0.2 smd: 2(-0.8,0.2) 3(-0.8,-0.2) 4(-0.8,-0.6) 9(0.8,-0.6) 10(0.8,-0.2) 11(0.8,0.2) 12(0.8,0.6)
  rect 0.2x0.6 smd: 5(-0.6,-1.2) 6(-0.2,-1.2) 7(0.2,-1.2) 8(0.6,-1.2) 13(0.6,1.2) 14(0.2,1.2) 15(-0.2,1.2) 16(-0.6,1.2)
  silkscreen extent -1.08,-1.33 1.08,1.45, body extent -0.92,-1.32 0.92,1.33, height 0.56
Samtec_QSH-030-01-X-D-A [mm] "Receptacle, 0.5 mm, 30x2, TH"
  rect 2.27x0.279 smd: 1(-2.865,7.25) 2(2.865,7.25) 3(-2.865,6.75) 4(2.865,6.75) 5(-2.865,6.25) 6(2.865,6.25) 7(-2.865,5.75) 8(2.865,5.75) 9(-2.865,5.25) 10(2.865,5.25) 11(-2.865,4.75) 12(2.865,4.75) 13(-2.865,4.25) 14(2.865,4.25) 15(-2.865,3.75) 16(2.865,3.75) 17(-2.865,3.25) 18(2.865,3.25) 19(-2.865,2.75) 20(2.865,2.75) 21(-2.865,2.25) 22(2.865,2.25) 23(-2.865,1.75) 24(2.865,1.75) 25(-2.865,1.25) 26(2.865,1.25) 27(-2.865,0.75) 28(2.865,0.75) 29(-2.865,0.25) 30(2.865,0.25) 31(-2.865,-0.25) 32(2.865,-0.25) 33(-2.865,-0.75) 34(2.865,-0.75) 35(-2.865,-1.25) 36(2.865,-1.25) 37(-2.865,-1.75) 38(2.865,-1.75) 39(-2.865,-2.25) 40(2.865,-2.25) 41(-2.865,-2.75) 42(2.865,-2.75) 43(-2.865,-3.25) 44(2.865,-3.25) 45(-2.865,-3.75) 46(2.865,-3.75) 47(-2.865,-4.25) 48(2.865,-4.25) 49(-2.865,-4.75) 50(2.865,-4.75) 51(-2.865,-5.25) 52(2.865,-5.25) 53(-2.865,-5.75) 54(2.865,-5.75) 55(-2.865,-6.25) 56(2.865,-6.25) 57(-2.865,-6.75) 58(2.865,-6.75) 59(-2.865,-7.25) 60(2.865,-7.25)
  round 0 hole 1.02 unplated: MH1(2.67,10.065) MH2(2.67,-10.065)
  rect 0.43x2.54 smd: MP1(0,8.065) MP4(0,-8.065)
  rect 0.43x4.7 smd: MP2(0,3.175) MP3(0,-3.175)
  silkscreen extent -3.9,-10.66 3.62,10.66, body extent -3.75,-10.64 3.75,10.67, height 3.25
SM_RADIAL_6.3BMM [mm] "Nichicon 6.3x7.7"
  rect 3.5x1.6 smd: 1(-2.7,0) 2(2.7,0)
  silkscreen extent -3.4,-3.4 3.4,3.4, body extent -3.4,-3.4 3.4,3.4, height 8
SML-E1_Yellow [mm] "SMD, 2-Leads, Body 1.6x0.8mm"
  rect 0.8x0.8 smd: 1(0.825,0) 2(-0.825,0)
  silkscreen extent -1.8,-0.8 1.3,0.8, body extent -0.85,-0.45 0.85,0.45, height 0.46
SML_Green_0805 [mm] "SMD, 2-Leads, Body 2x1.25mm"
  rrect8% 1.2x1.2 smd: 1(-1.05,0) 2(1.05,0)
  silkscreen extent -1.7,-1 2.3,1, body extent -1,-0.63 1,0.63, height 0.8
SOD-123 [mm] "On Semi recommended land pattern"
  rect 0.915x1.22 smd: 1(-1.637,0) 2(1.637,0)
  silkscreen extent -2.75,-1.17 2.03,1.17, body extent -1.93,-0.9 1.93,0.9, height 1.35
SOD-123W [mm] "NXP recommended land pattern"
  rect 1.2x1.2 smd paste-0.05: 1(-1.4,0) 2(1.4,0)
  silkscreen extent -2.64,-1.14 1.68,1.14, body extent -1.85,-0.95 1.85,0.95, height 1.1
SOD-128 [mm] "SMD, 2-Leads, Body 4x2.7mm, Height 1.1mm"
  rect 1.4x2.1 smd paste-0.1: 1(-2.2,0) 2(2.2,0)
  silkscreen extent -3.45,-1.45 2.95,1.45, body extent -2.5,-1.35 2.5,1.35, height 1.11
SOD-882 [mm] "Skyworks"
  rrect42% 0.475x0.75 smd mask+0.05: 1(-0.412,0) 2(0.412,0)
  silkscreen extent -1.1,-0.35 -0.87,0.35, body extent -0.5,-0.3 0.5,0.3, height 0.5
SOIC-8 [mm] "duplicate of SO-8.  SOIC, 8-Leads, Body 5.0x4.0mm (max), Pitch 1.27mm, IPC Medium Density"
  rrect17% 1.45x0.6 smd: 1(-2.725,1.905) 2(-2.725,0.635) 3(-2.725,-0.635) 4(-2.725,-1.905) 5(2.725,-1.905) 6(2.725,-0.635) 7(2.725,0.635) 8(2.725,1.905)
  silkscreen extent -3.5,-2.5 0.9,2.5, body extent -3,-2.45 3,2.45, height 1.63
SOT-23 [mm] "SOT23, 3-Leads, Body 2.9x1.3mm, Pitch 0.95mm, Lead Span 2.5mm, IPC Medium Density"
  rrect50% 1x0.6 smd: 1(-1.2,0.95) 2(-1.2,-0.95) 3(1.2,0)
  silkscreen extent -1.63,-1.5 0.7,1.5, body extent -1.16,-1.45 1.21,1.45, height 1
Sullins_GBC01SFBN-M30 [mil] "Header, 1x1, SMT"
  rrect8% 50x250 smd: 1(0,100)
  body extent -50,-50 50,150, height 490
SW_CJS_1201A [mm] "Copal- Electronics"
  rect 1x1.6 smd paste+0 mask+0.05: 1(-1.75,-1.15) 2(0,1.15) 3(1.75,-1.15)
  silkscreen extent -3,-1.6 -2.7,-0.8, body extent -3,-1.55 3,1.55, height 2.51
SW_KMR243GLFG [mm] "SMD, 5-Leads, Body 4.2x2.8mm"
  rrect11% 0.9x1 smd: 1(-2.05,0.8) 2(2.05,0.8) 3(-2.05,-0.8) 4(2.05,-0.8)
  rrect18% 1.7x0.55 smd: 5(0,1.425)
  silkscreen extent -3.1,0.7 -2.9,0.9, body extent -2.3,-1.4 2.3,1.4, height 1.92
TE_9-2304372-9 [mm] "Header(shrouded), 6 Power, 2 Signal, R/A, TH"
  rrect50% 1.5x1.5 hole 1: 1(-0.9,14)
  round 1.5 hole 1: 2(0.9,14) S1(-3.9,14) S2(-3.9,7) S3(-3.9,0) S4(3.9,14) S5(3.9,7) S6(3.9,0)
  round 2 hole 2.25 unplated: ALIGN1(0,0) ALIGN2(6.6,0)
  silkscreen extent -7.45,-5.15 10.3,15.95, body extent -7.45,-5.15 10.3,15.95, height 13.51
TI_Stacked_Overlay_Small [mil]
  silkscreen extent -418,-98 418,98
TLMx1000_Yellow [mm] "SMD, 2-Leads, Body 1.6x0.8mm"
  rrect17% 0.6x0.8 smd: 1(-0.725,0) 2(0.725,0)
  silkscreen extent -0.97,-0.8 1.6,0.8, body extent -0.85,-0.45 0.85,0.45, height 0.65
TP_25MIL-SMT [mil]
  round 25 smd paste-25 mask-2.5: 1(0,0)
TSSOP-8 [mm] "TSSOP, 8-Leads, Body 3.1x4.5mm (max), Pitch 0.65mm, IPC Medium Density"
  rrect50% 1.7x0.35 smd: 1(-2.85,0.975) 2(-2.85,0.325) 3(-2.85,-0.325) 4(-2.85,-0.975) 5(2.85,-0.975) 6(2.85,-0.325) 7(2.85,0.325) 8(2.85,0.975)
  silkscreen extent -2.97,-1.55 1.6,1.82, body extent -3.2,-1.55 3.2,1.55, height 1.07
TSW-102-07-G-S [mm] "Samtec 100mil, 1x2, 230 mil above insulator"
  rrect50% 1.65x1.65 hole 1.016: 1(-1.27,0)
  round 1.65 hole 1.016: 2(1.27,0)
  silkscreen extent -3.17,-1.27 2.54,1.27, body extent -2.54,-1.27 2.54,1.27, height 8.38
VCTA20161B [mm] "CYNTEC"
  rect 0.7x1.9 smd: 1(-0.8,0) 2(0.8,0)
  silkscreen extent -0.28,-1.1 0.28,1.1, body extent -1.1,-0.9 1.1,0.9, height 1.21
VGROVE_1-6_45A [mil]
WEEE_Minimum [mil] "WEEElie bin"
  silkscreen extent -95,-172 99,104
XEL4030_310 [mm] "SMD, 2-Leads, Body 4x4mm, Pitch 2.37mm"
  rect 0.98x3.9 smd: 1(-1.185,0) 2(1.185,0)
  silkscreen extent -2.3,-2.3 2.3,2.3, body extent -2.15,-2.15 2.15,2.15, height 3.1
XTAL_ABM3 [mm] "Abracon recommended land pattern 12.28.10"
  rect 1.9x2.4 smd: 1(-2.05,0) 2(2.05,0)
  silkscreen extent -2.67,-1.78 2.67,1.78, body extent -2.6,-1.7 2.6,1.7, height 1.3

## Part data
C1 C10 C48 C53 C56 C59 C60 C65 C87 C90 C145 C159 C183 C186 C187 C190 C192: library part CMP-0007136-5, "CAP, CERM, 1 uF, 16 V, +/- 10%, X7R, AEC-Q200 Grade 1, 0603", Cap_Case=0603, Manufacturer=MuRata, Supplier Part Number 1=490-5241-6-ND, TempCo=X7R, Tolerance_%=10%, Value1=Unknown, Value2=16V, ValueDisplayed=1uF
C2: library part CMP-0006325-2, "CAP, CERM, 0.1 uF, 50 V, +/- 10%, X7R, AEC-Q200 Grade 1, 0402", Cap_Case=0402, Manufacturer=TDK, Supplier Part Number 1=445-6899-1-ND, TempCo=X7R, Tolerance_%=10%, Value1="0.039064 ohm", Value2=50V, ValueDisplayed=0.1uF
C3 C8 C11 C24 C32 C35 C51 C123 C137 C146 C148 C149 C171: library part CMP-0007134-5, "CAP, CERM, 2.2 uF, 6.3 V, +/- 10%, X7R, AEC-Q200 Grade 1, 0603", Cap_Case=0603, Manufacturer=MuRata, Supplier Part Number 1=490-5316-1-ND, TempCo=X7R, Tolerance_%=10%, Value1=Unknown, Value2=6.3V, ValueDisplayed=2.2uF
C4 C152 C154 C182 C194 C198: library part CMP-0081061-1, "CAP, CERM, 10 µF, 10 V,+/- 5%, X7R, AEC-Q200 Grade 1, 0805", Cap_Case=0805, Manufacturer=Kemet, Supplier Part Number 1=399-15693-1-ND, TempCo=X7R, Tolerance_%=5%, Value2=10V, ValueDisplayed=10µF
C5 C21 C22 C55 C92 C96 C107 C111 C113 C115 C117 C119 C120 C122 C138 C139 C140 C141 C142 C163 C164 C165 C168 C170 C174 C175 C176 C177 C199: library part CMP-0078265-1, "CAP, CERM, 0.22 µF, 16 V,+/- 10%, X7R, AEC-Q200 Grade 1, 0402", Cap_Case=0402, Manufacturer=MuRata, Supplier Part Number 1=490-10671-1-ND, TempCo=X7R, Tolerance_%=10%, Value2=16V, ValueDisplayed=0.22µF
C6 C80 C144 C147 C153: library part CMP-0091520-1, "Cap Ceramic Multilayer 4.7uF 6.3V DC 10% SMD Paper T/R", Manufacturer=Murata, Operating Temperature Range="-55°C to +125°C", TempCo=22%, Temperature Characteristic=X7S, Tolerance_%=10%, ValueDisplayed=4.7uF
C7 C15 C31 C110 C112 C114 C116 C124 C125 C127 C129 C130 C132 C134: library part CMP-0008017-2, "CAP, CERM, 10 uF, 10 V, +/- 10%, X7R, 0805", Cap_Case=0805, Manufacturer=MuRata, Supplier Part Number 1=490-10674-1-ND, TempCo=X7R, Tolerance_%=10%, Value1=Unknown, Value2=10V, ValueDisplayed=10uF
C9 C58 C181: library part CMP-0088247-2, "3 Terminals Low ESL Chip Multilayer Ceramic Capacitors for Automotive", Manufacturer=Murata, Tolerance_%=20%, ValueDisplayed=1uF
C12 C13 C36 C46 C54 C105 C131 C135 C136 C150 C172 C178 C200: library part CMP-0006351-2, "CAP, CERM, 0.1 uF, 16 V, +/- 10%, X7R, 0402", Cap_Case=0402, Manufacturer=MuRata, Supplier Part Number 1=490-4759-2-ND, TempCo=X7R, Tolerance_%=10%, Value1=Unknown, Value2=16V, ValueDisplayed=0.1uF
C14 C17 C19 C57 C81 C158 C160 C184 C185 C188 C189 C191 C193: library part CMP-0006350-2, "CAP, CERM, 0.1 uF, 10 V, +/- 10%, X7R, AEC-Q200 Grade 1, 0402", Cap_Case=0402, Manufacturer=MuRata, Supplier Part Number 1=81-GCM155R71A104K5D, TempCo=X7R, Tolerance_%=10%, Value1=Unknown, Value2=10V, ValueDisplayed=0.1uF
C16 C20 C37 C44 C52: library part CMP-0006324-2, "CAP, CERM, 0.01 uF, 50 V, +/- 10%, X7R, AEC-Q200 Grade 1, 0402", Cap_Case=0402, Manufacturer=TDK, Supplier Part Number 1=445-6893-1-ND, TempCo=X7R, Tolerance_%=10%, Value1="0.333065 ohm", Value2=50V, ValueDisplayed=0.01uF
C18 C42 C43 C47 C49 C64 C67 C69 C71 C73 C75 C76 C77 C78 C82 C86 C88 C89 C91 C97 C98 C133: library part CMP-0078241-1, "CAP, CERM, 0.1 µF, 10 V,+/- 10%, X7R, 0402", Cap_Case=0402, Manufacturer=Kemet, Supplier Part Number 1=399-3520-1-ND, TempCo=X7R, Tolerance_%=10%, Value2=10V, ValueDisplayed=0.1µF
C23 C25 C26 C29: library part CMP-0008811-3, "CAP, CERM, 22 uF, 10 V, +/- 10%, X7R, AEC-Q200 Grade 1, 1206", Cap_Case=1206, Manufacturer=MuRata, TempCo=X7R, Tolerance_%=10%, Value1=Unknown, Value2=10V, ValueDisplayed=22uF
C27 C28: library part CMP-0089508-1, "C0603 0.10 μF X7R 30ppm/°C 10.00% 16 V", Digikey Part Number=399-6855-2-ND, Manufacturer=KEMET, Mouser Part Number=80-C0603C104K4RAUTO, Operating Temperature Range="-55°C to +125°C", TempCo=30ppm/°C, Temperature Characteristic=X7R, Tolerance_%=0.1%, ValueDisplayed="0.10 μF"
C30 C33: library part CMP-0860920-1, "CAP, CERM, 27 pF, 50 V,+/- 5%, C0G/NP0, AEC-Q200 Grade 1, 0402", Cap_Case=0402, Manufacturer=MuRata, TempCo=C0G/NP0, Tolerance_%=5%, Value2=50V, ValueDisplayed=27pF
C34: library part CMP-0006354-2, "CAP, CERM, 1000 pF, 50 V, +/- 10%, X7R, AEC-Q200 Grade 1, 0402", Cap_Case=0402, Manufacturer=MuRata, Supplier Part Number 1=490-4761-1-ND, TempCo=X7R, Tolerance_%=10%, Value1=Unknown, Value2=50V, ValueDisplayed=1000pF
C38: library part CMP-0007977-2, "CAP, CERM, 2.2 uF, 50 V, +/- 10%, X7R, AEC-Q200 Grade 1, 0805", Cap_Case=0805, Manufacturer=TDK, Supplier Part Number 1=445-174216-1-ND, TempCo=X7R, Tolerance_%=10%, Value1="0.003288 ohm", Value2=50V, ValueDisplayed=2.2uF
C39 C45: library part CMP-0007995-2, "CAP, CERM, 10 uF, 16 V, +/- 10%, X7R, 0805", Cap_Case=0805, Manufacturer="Samsung Electro-Mechanics", TempCo=X7R, Tolerance_%=10%, Value1=Unknown, Value2=16V, ValueDisplayed=10uF
C40: library part CMP-0006669-2, "CAP, CERM, 0.047 uF, 25 V, +/- 10%, X7R, 0402", Cap_Case=0402, Manufacturer=MuRata, Supplier Part Number 1=490-3254-1-ND, TempCo=X7R, Tolerance_%=10%, Value1=Unknown, Value2=25V, ValueDisplayed=0.047uF
C41 C61 C62: library part CMP-0006349-2, "CAP, CERM, 1 uF, 10 V, +/- 10%, X7S, AEC-Q200 Grade 1, 0402", Cap_Case=0402, Manufacturer=MuRata, Supplier Part Number 1=81-GCM155C71A105KE8D, TempCo=X7S, Tolerance_%=10%, Value1=Unknown, Value2=10V, ValueDisplayed=1uF
C50 C66 C109: library part CMP-0078218-1, "CAP, CERM, 0.01 µF, 16 V,+/- 10%, X7R, 0402", Cap_Case=0402, Manufacturer=Kemet, Supplier Part Number 1=399-1038-1-ND, TempCo=X7R, Tolerance_%=10%, Value2=16V, ValueDisplayed=0.01µF
C63 C70 C83 C84: library part CMP-0087060-3, "Cap Ceramic 8pF 50V C0G 0.5pF SMD 0402 125C Paper T/R", Manufacturer="Murata Electronics North America", TempCo=30ppm/°C
C68 C72 C79: library part CMP-0007058-4, "CAP, CERM, 4.7 uF, 10 V, +/- 10%, X7S, 0603", Cap_Case=0603, Manufacturer=TDK, Supplier Part Number 1=445-14258-1-ND, TempCo=X7S, Tolerance_%=10%, Value1=Unknown, Value2=10V, ValueDisplayed=4.7uF
C74 C85 C94: library part CMP-0006302-2, "CAP, CERM, 2.2 uF, 10 V, +/- 10%, X7S, 0402", Cap_Case=0402_065, Manufacturer=TDK, Supplier Part Number 1=445-9097-1-ND, TempCo=X7S, Tolerance_%=10%, Value1="0.005925 ohm", Value2=10V, ValueDisplayed=2.2uF
C93: library part CMP-0078217-1, "CAP, CERM, 15 pF, 50 V,+/- 1%, C0G/NP0, 0402", Cap_Case=0402, Manufacturer=AVX, Supplier Part Number 1=478-5126-1-ND, TempCo=C0G/NP0, Tolerance_%=1%, Value2=50V, ValueDisplayed=15pF
C95 C121: library part CMP-0007071-4, "CAP, CERM, 22 pF, 50 V, +/- 5%, C0G/NP0, AEC-Q200 Grade 1, 0603", Cap_Case=0603, Manufacturer=TDK, Supplier Part Number 1=445-5632-1-ND, TempCo=C0G/NP0, Tolerance_%=5%, Value1=Unknown, Value2=50V, ValueDisplayed=22pF
C99: library part CMP-0012608-3, "CAP, Polymer Hybrid, 68 uF, 35 V, +/- 20%, 35 ohm, 6.3x7.7 SMD", Manufacturer=Panasonic, Supplier Part Number 1=P15474CT-ND, Tolerance_%=20%, Value1="35 ohm", Value2=35V, ValueDisplayed=68uF
C100 C101: library part CMP-0008702-2, "CAP, CERM, 4.7 uF, 50 V, +/- 10%, X7R, 1206", Cap_Case=1206_180, Manufacturer=TDK, Supplier Part Number 1=445-8032-1-ND, TempCo=X7R, Tolerance_%=10%, Value1="0.003158 ohm", Value2=50V, ValueDisplayed=4.7uF
C102 C103: library part CMP-0088425-1, "1µF ±10% 6.3V Ceramic Capacitor X7R 0402 (1005 Metric)", Digikey Part Number=490-18216-1-ND, Manufacturer=Murata, Mouser Part Number=81-GRT155R70J105KE1D, Operating Temperature Range="-55°C to +125°C", TempCo=15%, Temperature Characteristic=X7R, Tolerance_%=10%, ValueDisplayed=1uF
C104 C126: library part CMP-0007104-4, "CAP, CERM, 0.1 uF, 50 V, +/- 10%, X8R, AEC-Q200 Grade 0, 0603", Cap_Case=0603, Manufacturer=TDK, Supplier Part Number 1=445-12606-1-ND, TempCo=X8R, Tolerance_%=10%, Value1=Unknown, Value2=50V, ValueDisplayed=0.1uF
C106 C108: library part CMP-0048219-1, "Ceramic Capacitor for Automotive 3.9pF ±0.1pF 50VDC C0G 0402 Paper T/R", Manufacturer=Murata, Operating Temperature Range="-55°C to +125°C", TempCo=30ppm/°C, Temperature Characteristic=C0G, ValueDisplayed=3.9pF
C118 C173: library part CMP-0090082-1, "Cap Ceramic 4.7uF 50V X7R 10% Pad SMD 0805 +125°C Automotive T/R", Manufacturer="TDK Corporation", Operating Temperature Range="-55°C to +125°C", TempCo=15%, Temperature Characteristic=X7R, Tolerance_%=0.1%, ValueDisplayed=4.7uF
C128 C143 C151 C169: library part CMP-0860846-1, "CAP, CERM, 22 µF, 6.3 V,+/- 20%, X7T, AEC-Q200 Grade 1, 0805", Cap_Case=0805, Manufacturer=TDK, TempCo=X7T, Tolerance_%=20%, Value2=6.3V, ValueDisplayed=22µF
C155 C166: library part CMP-0120220-1, "47 pF ±1% 50V Ceramic Capacitor C0G, NP0 0402 (1005 Metric)", Digikey Part Number=478-KGM05ACG1H470FHCT-ND, Manufacturer="KYOCERA AVX", Mouser Part Number=581-KGM05ACG1H470FH, Operating Temperature Range="-55°C to +125°C", TempCo=30ppm/°C, Temperature Characteristic=C0G, Tolerance_%=1%, ValueDisplayed=47pF
C156 C162: library part CMP-0120219-1, "22 pF ±1% 50V Ceramic Capacitor C0G, NP0 0402 (1005 Metric)", Digikey Part Number=478-KGM05ACG1H220FHCT-ND, Manufacturer="KYOCERA AVX", Mouser Part Number=581-KGM05ACG1H220FH, Operating Temperature Range="-55°C to +125°C", TempCo=30ppm/°C, Temperature Characteristic=C0G, Tolerance_%=1%, ValueDisplayed=22pF
C157 C161: library part CMP-0007969-2, "CAP, CERM, 0.1 uF, 100 V, +/- 10%, X7R, AEC-Q200 Grade 1, 0805", Cap_Case=0805, Manufacturer=TDK, Supplier Part Number 1=445-5827-1-ND, TempCo=X7R, Tolerance_%=10%, Value1="0.020726 ohm", Value2=100V, ValueDisplayed=0.1uF
C167: library part CMP-0120216-1, "4700 pF ±10% 1000V (1kV) Ceramic Capacitor X7R 1206 (3216 Metric)", Digikey Part Number=311-1971-1-ND, Manufacturer=YAGEO, Mouser Part Number=603-CC126KKX7RCBB472, Operating Temperature Range="-55°C to +125°C", TempCo=15%, Temperature Characteristic=X7R, Tolerance_%=10%, ValueDisplayed=4.7nF
C180: library part CMP-0006330-2, "CAP, CERM, 0.047 uF, 50 V, +/- 10%, X7R, AEC-Q200 Grade 1, 0402", Cap_Case=0402, Manufacturer=TDK, Supplier Part Number 1=445-6897-1-ND, TempCo=X7R, Tolerance_%=10%, Value1="0.06407 ohm", Value2=50V, ValueDisplayed=0.047uF
C195: library part CMP-0007094-5, "CAP, CERM, 0.22 uF, 50 V, +/- 10%, X7R, AEC-Q200 Grade 1, 0603", Cap_Case=0603, Manufacturer=TDK, Supplier Part Number 1=445-6926-1-ND, TempCo=X7R, Tolerance_%=10%, Value1="0.021699 ohm", Value2=50V, ValueDisplayed=0.22uF
"CAUTION HOT SURFACE1": library part CMP-0074837-1, "IEC 61010-1 Hot Surface Warning"
D1: library part CMP-0078196-2, "LED, Yellow, SMD", Color=yellow, Manufacturer=Vishay-Semiconductor, Power_TotalModule=40mW, Value1=.04W, Value2=1.8V
D2 D4 D5: library part CMP-0078187-3, "Diode, Schottky,  V, 0.01 A, SOD-882", Manufacturer="Skyworks Solutions", Value1=0.01A, Value2=0.34V
D3: library part CMP-0005735-3, "Diode, TVS, Bi, 28 V, 45.4 Vc, AEC-Q101, SOD-123", Manufacturer="Comchip Technology", Value1=200W
D6 D12: library part CMP-0003042-3, "LED, Green, SMD", Color=Green, Manufacturer=Lumex, Power_TotalModule=50mW, Value1=0.05W, Value2=2V
D7 D8 DS2: library part CMP-0002902-2, "LED, Red, SMD", Color=Red, Manufacturer=OSRAM, Value1=W, Value2=1.8V
D9 D13: library part CMP-0002977-3, "LED, Yellow, SMD", Color=yellow, Manufacturer=Rohm, Power_TotalModule=54mW, Value1=0.054W, Value2=2.2V
D10: library part CMP-0120222-1, "Yellow 590nm LED Indication - Discrete 2.1V 0402 (1006 Metric)", Color=Yellow, Digikey Part Number=846-1204-1-ND, Forward Current=20mA, Manufacturer="Rohm Semiconductor", Mouser Part Number=755-SML-P12YTT86R, Operating Temperature Range="-40°C to +85°C", Power_TotalModule=52mW
D11: library part CMP-0077017-3, "Diode, Schottky, 30 V, 5 A, SOD-128", Manufacturer=Nexperia, Value1=5A, Value2=0.36V
D14: library part CMP-0120221-1, "LED Uni-Color Orange 2-Pin Chip 0402(1006Metric) T/R", Color=Orange, Digikey Part Number=846-1200-1-ND, Forward Current=20mA, Manufacturer="Rohm Semiconductor", Mouser Part Number=755-SML-P12DTT86R, Operating Temperature Range="-40°C to +85°C", Power_TotalModule=52mW
D15 D17 D18 D19: library part CMP-0073591-4, "Automotive 1-Channel Ultra-Low-Capacitance IEC ESD Protection Diode, DPY0002A (X1SON-2)", Alternate Manufacturer="Texas Instruments", Alternate PartNumber=TPD1E05U06QDPYTQ1, Operating Temperature Range="-40 to 125 C", Rating=Automotive
D16: library part CMP-0076989-2, "Diode, Schottky, 60 V, 2 A, SOD-123W", Manufacturer=Nexperia, Value1=2A, Value2=0.53V
"ESD Susceptible1": library part CMP-0074840-1, "ESD Susceptible Symbol"
FB1: library part CMP-0003348-2, "Ferrite Bead, 1000 ohm @ 100 MHz, 0.6 A, 0603", Manufacturer=MuRata, Supplier Part Number 1=490-5215-1-ND, Value1="0.35 ohm", Value2=0.6A, ValueDisplayed="1000 ohm"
